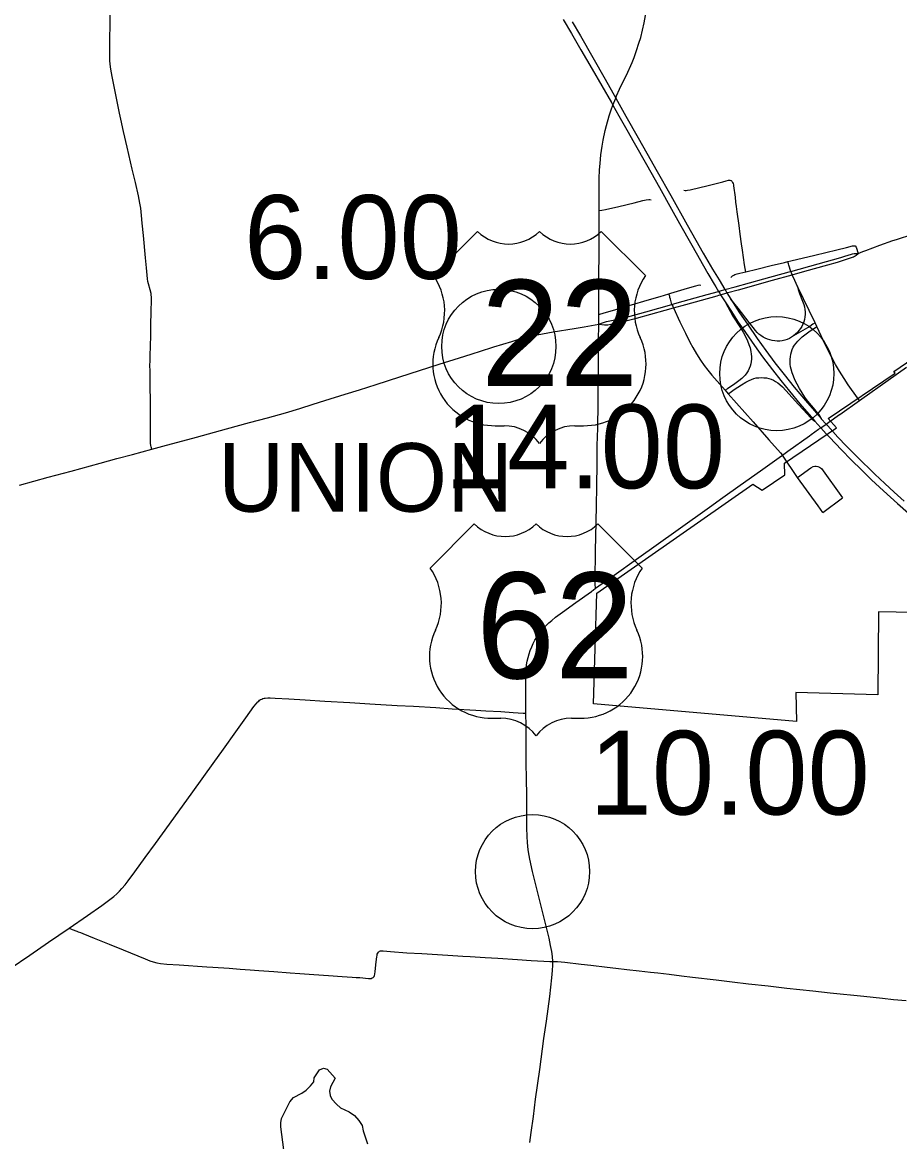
# Model space of a CAD drawing. Extents: x 1597222 to 1925846, y 496284 to 911751.
# Drawn here: x 1687037 to 1698562, y 546977 to 561679 of the extents above; entities that cross this region are included whole.
import ezdxf

# ---------------------------------------------------------------- set-up
doc = ezdxf.new("R2010")
doc.units = 0
for name, color, linetype in [('Default', 7, 'Continuous'), ('GM_X_City_Street', 7, 'Continuous'), ('GM_X_Corporation', 7, 'Continuous'), ('GM_X_County_Road', 7, 'Continuous'), ('GM_X_Interchange_Ramps', 7, 'Continuous'), ('GM_X_Township', 7, 'Continuous'), ('GM_X_Township_Road', 7, 'Continuous'), ('GM_X_Township_Text', 7, 'Continuous'), ('GM_X_US_Route', 7, 'Continuous'), ('GM_X_US_Shield', 7, 'Continuous')]:
    doc.layers.add(name, color=color, linetype=linetype)

msp = doc.modelspace()

# ---------------------------------------------------------------- linework, layer by layer
at = {"layer": 'Default'}
for centre in [(1693296, 557422), (1693296, 557422), (1696948, 557065), (1696948, 557065), (1693739, 550524), (1693739, 550524)]:
    msp.add_circle(centre, 750, dxfattribs=at)
at = {"layer": 'GM_X_City_Street'}
for points in [[(1697222, 555701), (1697022, 555995)], [(1697222, 555701), (1697395, 555827), (1697425, 555845), (1697448, 555850), (1697467, 555850), (1697488, 555845), (1697511, 555835), (1697534, 555818), (1697809, 555433)], [(1697552, 555243), (1697491, 555328), (1697222, 555701)], [(1697552, 555243), (1697809, 555433)]]:
    msp.add_lwpolyline(points, dxfattribs=at)
at = {"layer": 'GM_X_Corporation'}
msp.add_lwpolyline([(1699439, 553916), (1698284, 553936), (1698274, 552846), (1697199, 552875), (1697209, 552495), (1694539, 552727), (1694583, 554182), (1696634, 555612), (1696755, 555535), (1697055, 555734), (1697051, 555890), (1697732, 556354), (1697623, 556477), (1698504, 557069), (1698487, 557093), (1699412, 557730)], dxfattribs=at)
at = {"layer": 'GM_X_County_Road'}
for points in [[(1695047, 561154), (1695073, 561218), (1695107, 561311), (1695137, 561404), (1695160, 561482), (1695184, 561577), (1695205, 561673), (1695223, 561770), (1695241, 561899), (1695259, 562046), (1695292, 562306), (1695295, 562326)], [(1694615, 559208), (1694615, 559348), (1694614, 559495), (1694615, 559626), (1694620, 559741), (1694626, 559823), (1694637, 559937), (1694653, 560051), (1694667, 560132), (1694694, 560260), (1694710, 560324), (1694746, 560450), (1694772, 560528), (1694795, 560593), (1694832, 560685), (1694843, 560712), (1694883, 560802), (1694990, 561023), (1695030, 561112), (1695047, 561154)], [(1694610, 558339), (1694611, 558348), (1694614, 558643), (1694615, 558791), (1694615, 559020), (1694615, 559168), (1694615, 559208)], [(1697093, 558536), (1697131, 558545), (1697449, 558622), (1697736, 558692), (1697863, 558724), (1697943, 558742), (1697960, 558745), (1697978, 558742), (1697990, 558727), (1698018, 558645)], [(1696536, 558403), (1696541, 558404), (1696684, 558438), (1696875, 558485), (1697051, 558526), (1697093, 558536)], [(1697132, 558408), (1697107, 558490), (1697101, 558508), (1697093, 558536)], [(1696342, 558329), (1696368, 558349), (1696383, 558358), (1696398, 558365), (1696429, 558375), (1696536, 558403)], [(1694608, 557841), (1694608, 557863), (1694608, 557969), (1694608, 558135), (1694609, 558216)], [(1694609, 558216), (1694610, 558339)], [(1695531, 558115), (1695556, 558122), (1695776, 558187), (1695885, 558220), (1695917, 558228), (1695933, 558230), (1695949, 558228)], [(1694608, 557841), (1694679, 557862), (1694789, 557893), (1695008, 557958), (1695274, 558038), (1695416, 558080), (1695531, 558115)], [(1695571, 557974), (1695550, 558042), (1695544, 558066), (1695541, 558078), (1695531, 558115)], [(1694610, 557713), (1694609, 557764), (1694608, 557841)], [(1694566, 554246), (1694561, 554299), (1694561, 554365), (1694567, 554726), (1694572, 554939), (1694575, 555103), (1694578, 555349), (1694582, 555562), (1694587, 555906), (1694590, 556119), (1694596, 556348), (1694601, 556676), (1694603, 556922), (1694604, 557086), (1694605, 557332), (1694606, 557496), (1694610, 557713)], [(1687650, 549782), (1687892, 549949), (1688080, 550080), (1688187, 550156), (1688239, 550197), (1688276, 550230), (1688311, 550265), (1688345, 550301), (1688388, 550351), (1688428, 550403), (1688515, 550522), (1688651, 550708), (1688785, 550894), (1688968, 551146), (1689276, 551571), (1689544, 551945), (1689677, 552131), (1689840, 552358), (1689973, 552545), (1690078, 552691), (1690108, 552730), (1690130, 552754), (1690142, 552765), (1690154, 552775), (1690167, 552783), (1690181, 552790), (1690196, 552796), (1690212, 552801), (1690227, 552804), (1690260, 552807), (1690292, 552807), (1690357, 552804), (1690537, 552793), (1690750, 552780), (1691012, 552764), (1691340, 552745), (1691602, 552730), (1691962, 552707), (1692175, 552696), (1692470, 552678), (1692683, 552664), (1692994, 552646), (1693125, 552638), (1693321, 552626), (1693485, 552616), (1693616, 552607), (1693652, 552604)], [(1686464, 548967), (1686635, 549084), (1686878, 549251), (1687135, 549428), (1687378, 549596), (1687650, 549782)]]:
    msp.add_lwpolyline(points, dxfattribs=at)
at = {"layer": 'GM_X_Interchange_Ramps'}
for points in [[(1697222, 558208), (1697227, 558181), (1697230, 558171), (1697234, 558157), (1697243, 558130), (1697248, 558116), (1697287, 558019), (1697303, 557973), (1697311, 557941), (1697317, 557909), (1697320, 557876), (1697320, 557843), (1697317, 557810), (1697311, 557778), (1697302, 557746), (1697290, 557716), (1697276, 557686), (1697259, 557658), (1697239, 557631), (1697218, 557607), (1697194, 557584), (1697169, 557563), (1697142, 557544), (1697114, 557527), (1697084, 557514), (1697053, 557504), (1697020, 557497), (1696988, 557493), (1696955, 557492), (1696922, 557494), (1696889, 557499), (1696858, 557507), (1696826, 557517), (1696796, 557530), (1696768, 557546), (1696740, 557564), (1696714, 557585), (1696690, 557607), (1696668, 557631), (1696636, 557669), (1696587, 557735), (1696440, 557926), (1696344, 558044)], [(1696270, 558007), (1696371, 557821), (1696463, 557681), (1696505, 557611), (1696536, 557553), (1696563, 557494), (1696581, 557448), (1696596, 557402), (1696608, 557354), (1696613, 557322), (1696616, 557289), (1696615, 557257), (1696612, 557224), (1696606, 557192), (1696596, 557161), (1696584, 557131), (1696570, 557101), (1696553, 557074), (1696533, 557047), (1696512, 557023), (1696488, 557000), (1696450, 556969), (1696397, 556931), (1696302, 556867), (1696268, 556846)], [(1697530, 556477), (1697521, 556496), (1697512, 556512), (1697503, 556527), (1697493, 556540), (1697484, 556552), (1697428, 556615), (1697356, 556705), (1697317, 556758), (1697280, 556812), (1697246, 556868), (1697214, 556926), (1697185, 556985), (1697166, 557030), (1697149, 557076), (1697136, 557124), (1697130, 557156), (1697125, 557189), (1697123, 557221), (1697123, 557254), (1697126, 557287), (1697131, 557319), (1697140, 557351), (1697151, 557382), (1697165, 557411), (1697182, 557439), (1697201, 557466), (1697223, 557491), (1697245, 557515), (1697282, 557548), (1697334, 557588), (1697387, 557626), (1697442, 557662), (1697473, 557683)], [(1697450, 557731), (1697423, 557714), (1697380, 557686), (1697169, 557563)], [(1696309, 556800), (1696335, 556818), (1696389, 556857), (1696486, 556920), (1696542, 556954), (1696586, 556977), (1696616, 556990), (1696647, 557000), (1696679, 557008), (1696712, 557012), (1696745, 557014), (1696778, 557012), (1696811, 557008), (1696843, 557001), (1696874, 556991), (1696905, 556978), (1696933, 556962), (1696961, 556944), (1696987, 556924), (1697023, 556890), (1697068, 556842), (1697233, 556659), (1697296, 556592), (1697394, 556485), (1697413, 556467), (1697449, 556441)]]:
    msp.add_lwpolyline(points, dxfattribs=at)
at = {"layer": 'GM_X_Township'}
msp.add_lwpolyline([(1690483, 546771), (1690434, 547171), (1690433, 547223), (1690443, 547283), (1690550, 547502), (1690599, 547555), (1690710, 547616), (1690765, 547653), (1690824, 547709), (1690866, 547762), (1690871, 547814), (1690941, 547919), (1690991, 547941), (1691043, 547928), (1691146, 547810), (1691084, 547696), (1691073, 547642), (1691080, 547585), (1691104, 547533), (1691163, 547468), (1691217, 547423), (1691330, 547368), (1691398, 547319), (1691457, 547256), (1691502, 547189), (1691516, 547119), (1691572, 546950)], dxfattribs=at)
at = {"layer": 'GM_X_Township_Road'}
for points in [[(1688737, 556073), (1688728, 556105), (1688724, 556121), (1688720, 556153), (1688718, 556202), (1688719, 556383), (1688719, 556530), (1688718, 556612), (1688718, 556711), (1688717, 556891), (1688717, 556989), (1688714, 557087), (1688713, 557186), (1688714, 557218), (1688714, 557234), (1688714, 557283), (1688715, 557316), (1688718, 557414), (1688723, 557578), (1688724, 557676), (1688724, 557742), (1688727, 557840), (1688728, 557873), (1688729, 557889), (1688733, 558020), (1688733, 558069), (1688730, 558102), (1688727, 558118), (1688717, 558166), (1688695, 558245), (1688687, 558277), (1688682, 558309), (1688670, 558407), (1688667, 558456), (1688656, 558587), (1688627, 558880), (1688612, 559043), (1688603, 559141), (1688592, 559239), (1688582, 559304), (1688562, 559400), (1688522, 559576), (1688481, 559751), (1688415, 560039), (1688367, 560246), (1688329, 560406), (1688311, 560486), (1688263, 560726), (1688215, 560967), (1688198, 561064), (1688190, 561129), (1688186, 561178), (1688185, 561244), (1688186, 561375), (1688187, 561489), (1688188, 561621), (1688190, 561866)], [(1695727, 559475), (1695743, 559472), (1695759, 559472), (1695776, 559474), (1695808, 559480), (1696046, 559536), (1696237, 559584), (1696284, 559598), (1696315, 559607), (1696331, 559607), (1696346, 559602), (1696347, 559602), (1696358, 559591), (1696367, 559577), (1696373, 559562), (1696377, 559546), (1696380, 559530), (1696399, 559384), (1696407, 559319), (1696415, 559260)], [(1694615, 559208), (1694650, 559214), (1694698, 559222), (1694871, 559262), (1695076, 559310), (1695187, 559337), (1695234, 559347), (1695266, 559351), (1695282, 559352), (1695299, 559350)], [(1696415, 559260), (1696424, 559189), (1696448, 559011), (1696464, 558898), (1696480, 558768), (1696491, 558687), (1696519, 558493), (1696528, 558445), (1696536, 558403)], [(1687650, 549782), (1687693, 549765), (1687754, 549740), (1687769, 549735), (1687799, 549724), (1687829, 549712), (1687981, 549651), (1688178, 549569), (1688360, 549495), (1688649, 549378), (1688710, 549353), (1688756, 549337), (1688804, 549325), (1688852, 549318), (1688934, 549310), (1689098, 549298), (1689458, 549273), (1689540, 549268), (1689752, 549255), (1689899, 549243), (1690030, 549232), (1690145, 549224), (1690341, 549211), (1690553, 549196), (1690684, 549186), (1690864, 549173), (1691060, 549159), (1691240, 549147), (1691371, 549139), (1691421, 549134), (1691469, 549131), (1691584, 549122), (1691601, 549121), (1691617, 549122), (1691633, 549127), (1691646, 549135), (1691657, 549147), (1691663, 549161), (1691668, 549177), (1691672, 549210), (1691686, 549341), (1691694, 549406), (1691696, 549422), (1691700, 549439), (1691707, 549454), (1691715, 549467), (1691728, 549477), (1691742, 549482), (1691758, 549484), (1691775, 549484), (1691873, 549475), (1692086, 549459), (1692283, 549448), (1692626, 549428), (1692823, 549415), (1692921, 549408), (1693052, 549400), (1693117, 549396), (1693281, 549385), (1693543, 549368), (1693723, 549357), (1693805, 549352), (1693886, 549347), (1693968, 549345), (1694005, 549345)], [(1694005, 549345), (1694017, 549345), (1694066, 549343), (1694164, 549333), (1694376, 549308), (1694506, 549294), (1694718, 549269), (1694832, 549255), (1694978, 549240), (1695141, 549221), (1695288, 549204), (1695386, 549193), (1695532, 549176), (1695695, 549156), (1695842, 549138), (1696151, 549102), (1696363, 549076), (1696575, 549051), (1696835, 549022), (1697080, 548994), (1697422, 548956), (1697651, 548933), (1698091, 548887), (1698336, 548862), (1698482, 548846), (1698646, 548829)]]:
    msp.add_lwpolyline(points, dxfattribs=at)
at = {"layer": 'GM_X_US_Route'}
for points in [[(1694140, 561715), (1694251, 561533), (1694375, 561320), (1694522, 561064), (1694778, 560625), (1694779, 560623)], [(1694258, 561686), (1694368, 561503), (1694531, 561219), (1694692, 560933), (1694832, 560685), (1694965, 560447), (1695127, 560162), (1695240, 559962), (1695377, 559719), (1695554, 559405), (1695772, 559020), (1695884, 558820), (1695982, 558649), (1696105, 558436), (1696189, 558295), (1696267, 558168), (1696277, 558153), (1696293, 558126), (1696344, 558044), (1696460, 557865), (1696561, 557715), (1696691, 557527), (1696806, 557367), (1696924, 557209), (1697044, 557053), (1697178, 556887), (1697325, 556710), (1697530, 556477), (1697533, 556473), (1697596, 556403), (1697618, 556379), (1697749, 556231), (1697862, 556113), (1698002, 555974), (1698237, 555745), (1698367, 555620), (1698488, 555509), (1698623, 555390)], [(1694779, 560623), (1694795, 560593), (1694874, 560453), (1694979, 560268), (1695076, 560097), (1695237, 559811), (1695406, 559511), (1695566, 559224), (1695668, 559037), (1695830, 558752), (1696041, 558382), (1696124, 558240), (1696146, 558205)], [(1698519, 558828), (1698611, 558857), (1698645, 558867), (1698658, 558871), (1698723, 558890), (1698784, 558907), (1698878, 558934), (1699005, 558965), (1699149, 558997), (1699324, 559033), (1699432, 559056), (1699504, 559071)], [(1698018, 558645), (1698077, 558668), (1698117, 558682), (1698303, 558752), (1698471, 558813), (1698519, 558828)], [(1694610, 557713), (1694673, 557737), (1694711, 557748), (1694755, 557759), (1694862, 557782), (1694989, 557813), (1695227, 557877), (1695571, 557974), (1695595, 557980), (1695639, 557993), (1696034, 558103), (1696184, 558144), (1696208, 558151), (1696267, 558168), (1696399, 558203), (1696778, 558310), (1697111, 558403), (1697132, 558408), (1697490, 558508), (1697791, 558592), (1697843, 558608), (1697931, 558635), (1697944, 558638), (1697964, 558642), (1697987, 558644), (1698018, 558645)], [(1696440, 558165), (1696447, 558167), (1696890, 558292), (1697150, 558364), (1697317, 558410), (1697619, 558494), (1697747, 558531), (1697824, 558554), (1697865, 558567), (1697954, 558601), (1697968, 558606), (1697982, 558614), (1697991, 558620), (1698018, 558645)], [(1698033, 556711), (1698008, 556746), (1697885, 556920), (1697831, 557002), (1697770, 557099), (1697721, 557184), (1697666, 557285), (1697593, 557432), (1697473, 557683), (1697450, 557731), (1697222, 558208), (1697185, 558288), (1697150, 558364), (1697139, 558389), (1697132, 558408)], [(1694610, 557713), (1694686, 557705), (1694728, 557707), (1694769, 557713), (1694929, 557750), (1695104, 557794), (1695483, 557898), (1695591, 557928), (1695752, 557973), (1695957, 558032), (1696163, 558089), (1696185, 558095)], [(1696146, 558205), (1696184, 558144), (1696198, 558121), (1696210, 558102), (1696270, 558007), (1696353, 557880), (1696441, 557743), (1696497, 557662), (1696656, 557433), (1696762, 557287), (1696890, 557117), (1697001, 556975), (1697114, 556834), (1697250, 556670), (1697401, 556497), (1697449, 556441), (1697527, 556354)], [(1696185, 558095), (1696210, 558102), (1696277, 558121)], [(1696277, 558121), (1696293, 558126), (1696297, 558127)], [(1696297, 558127), (1696305, 558129), (1696440, 558165)], [(1695571, 557974), (1695581, 557950), (1695591, 557928), (1695676, 557745), (1695747, 557597), (1695806, 557480), (1695844, 557408), (1695894, 557324), (1695947, 557241), (1695994, 557174), (1696043, 557109), (1696095, 557045), (1696268, 556846), (1696309, 556800), (1696637, 556430), (1696844, 556197), (1696995, 556025), (1697022, 555995)], [(1693716, 557555), (1693800, 557573), (1694010, 557612), (1694286, 557656), (1694416, 557678), (1694610, 557713)], [(1693203, 557408), (1693231, 557417), (1693466, 557489), (1693545, 557512), (1693688, 557549), (1693716, 557555)], [(1686997, 555600), (1687377, 555703), (1687677, 555785), (1688057, 555888), (1688278, 555950), (1688484, 556005), (1688737, 556073), (1688880, 556112), (1689323, 556231), (1689719, 556338), (1690020, 556421), (1690257, 556485), (1690494, 556552), (1690683, 556608), (1690855, 556662), (1691012, 556711), (1691278, 556794), (1691466, 556852), (1691684, 556922), (1691996, 557024), (1692512, 557188), (1692778, 557273), (1692934, 557322), (1693203, 557408)], [(1697774, 556529), (1698033, 556711), (1698066, 556735), (1698413, 556980), (1698651, 557150)], [(1697498, 556335), (1697527, 556354), (1697596, 556403), (1697631, 556428), (1697773, 556528), (1697774, 556529)], [(1697378, 556249), (1697399, 556264), (1697498, 556335)], [(1697527, 556354), (1697598, 556276)], [(1696979, 555964), (1697022, 555995), (1697092, 556045), (1697378, 556249)], [(1697598, 556276), (1697640, 556230), (1697797, 556062), (1697923, 555934), (1698063, 555795), (1698193, 555671), (1698349, 555525), (1698532, 555361), (1698680, 555231), (1698830, 555104), (1698969, 554990), (1699111, 554878), (1699202, 554810), (1699281, 554750), (1699444, 554631)], [(1694537, 554223), (1694566, 554246), (1694813, 554419), (1695107, 554628), (1695653, 555018), (1696066, 555313), (1696239, 555437), (1696466, 555599), (1696732, 555789), (1696979, 555964)], [(1693652, 552604), (1693652, 552618), (1693651, 552832), (1693650, 553061), (1693651, 553143), (1693654, 553192), (1693661, 553240), (1693670, 553289), (1693681, 553336), (1693694, 553383), (1693710, 553430), (1693728, 553475), (1693749, 553520), (1693771, 553563), (1693797, 553605), (1693824, 553645), (1693854, 553684), (1693885, 553722), (1693919, 553758), (1693954, 553792), (1693991, 553824), (1694042, 553865), (1694133, 553934), (1694307, 554058), (1694512, 554203)], [(1694512, 554203), (1694524, 554212), (1694537, 554223)], [(1693705, 546968), (1693722, 547096), (1693750, 547308), (1693780, 547535), (1693833, 547925), (1693888, 548332), (1693921, 548560), (1693965, 548882), (1693993, 549129), (1694003, 549227), (1694006, 549293), (1694005, 549342), (1694005, 549345), (1694000, 549408), (1693992, 549473), (1693977, 549554), (1693956, 549651), (1693909, 549842), (1693869, 550001), (1693786, 550335), (1693740, 550527), (1693704, 550687), (1693686, 550783), (1693676, 550848), (1693671, 550913), (1693668, 550978), (1693665, 551109), (1693665, 551273), (1693663, 551437), (1693662, 551536), (1693659, 551733), (1693656, 551962), (1693655, 552143), (1693655, 552290), (1693654, 552438), (1693652, 552604)]]:
    msp.add_lwpolyline(points, dxfattribs=at)
at = {"layer": 'GM_X_US_Shield'}
for p, q in [((1693018, 558933), (1692438, 558353)), ((1695222, 558353), (1694642, 558933)), ((1693250, 556381), (1693366, 556381)), ((1694294, 556381), (1694410, 556381)), ((1692974, 555092), (1692394, 554512)), ((1695178, 554512), (1694598, 555092)), ((1693206, 552539), (1693322, 552539)), ((1694250, 552539), (1694366, 552539))]:
    msp.add_line(p, q, dxfattribs=at)
for centre, radius, start, end in [((1693424, 559347), 580, 225.573, 314.427), ((1694236, 559347), 580, 225.573, 314.427), ((1691773, 557887), 812, 334.5471, 35.0009), ((1695888, 557887), 812, 144.9991, 205.4529), ((1693241, 557193), 812, 154.8319, 270.6383), ((1694419, 557193), 812, 269.3617, 25.1681), ((1693366, 555801), 580, 36.8699, 90), ((1694294, 555801), 580, 90, 143.1301), ((1693380, 555506), 580, 225.573, 314.427), ((1694192, 555506), 580, 225.573, 314.427), ((1691729, 554046), 812, 334.5471, 35.0009), ((1695844, 554046), 812, 144.9991, 205.4529), ((1693197, 553351), 812, 154.8319, 270.6383), ((1694375, 553351), 812, 269.3617, 25.1681), ((1693322, 551959), 580, 36.8699, 90), ((1694250, 551959), 580, 90, 143.1301)]:
    msp.add_arc(centre, radius, start, end, dxfattribs=at)

# ---------------------------------------------------------------- texts
at = {"layer": 'Default'}
for s, p in [('6.00', (1689949, 558310)), ('6.00', (1689949, 558310)), ('14.00', (1692588, 555559)), ('14.00', (1692588, 555559)), ('10.00', (1694489, 551274)), ('10.00', (1694489, 551274))]:
    msp.add_text(s, height=1100, dxfattribs=at).set_placement(p)
at = {"layer": 'GM_X_Township_Text'}
msp.add_text('UNION', height=900, rotation=0, dxfattribs=at).set_placement((1689608, 555252))
at = {"layer": 'GM_X_US_Shield'}
for s, p in [('22', (1693060, 556903)), ('62', (1692998, 553062))]:
    msp.add_text(s, height=1392.2, dxfattribs=at).set_placement(p)

doc.saveas('drawing.dxf')
